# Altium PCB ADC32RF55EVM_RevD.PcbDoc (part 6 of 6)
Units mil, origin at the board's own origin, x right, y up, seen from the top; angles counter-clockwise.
Board outline 4190 x 2750 mil, 14 copper layers (Top Copper, Layer 2 (GND1), Layer 3 (PWR1), Layer 4 (GND2, Layer 5 (PWR2), Layer 6 (GND3), Layer 7 (SIG1), Layer 8 (GND4), Layer 9 (GND5), Layer 10 (SIG2), Layer 11 (GND6), Layer 12 (PWR3), Layer 13 (GND7), Bottom Copper), stack 58.6 mil thick; 427 components, 558 nets, 1902 pads, 1008 vias.
Unrouted connection lines stored in the file: 51.
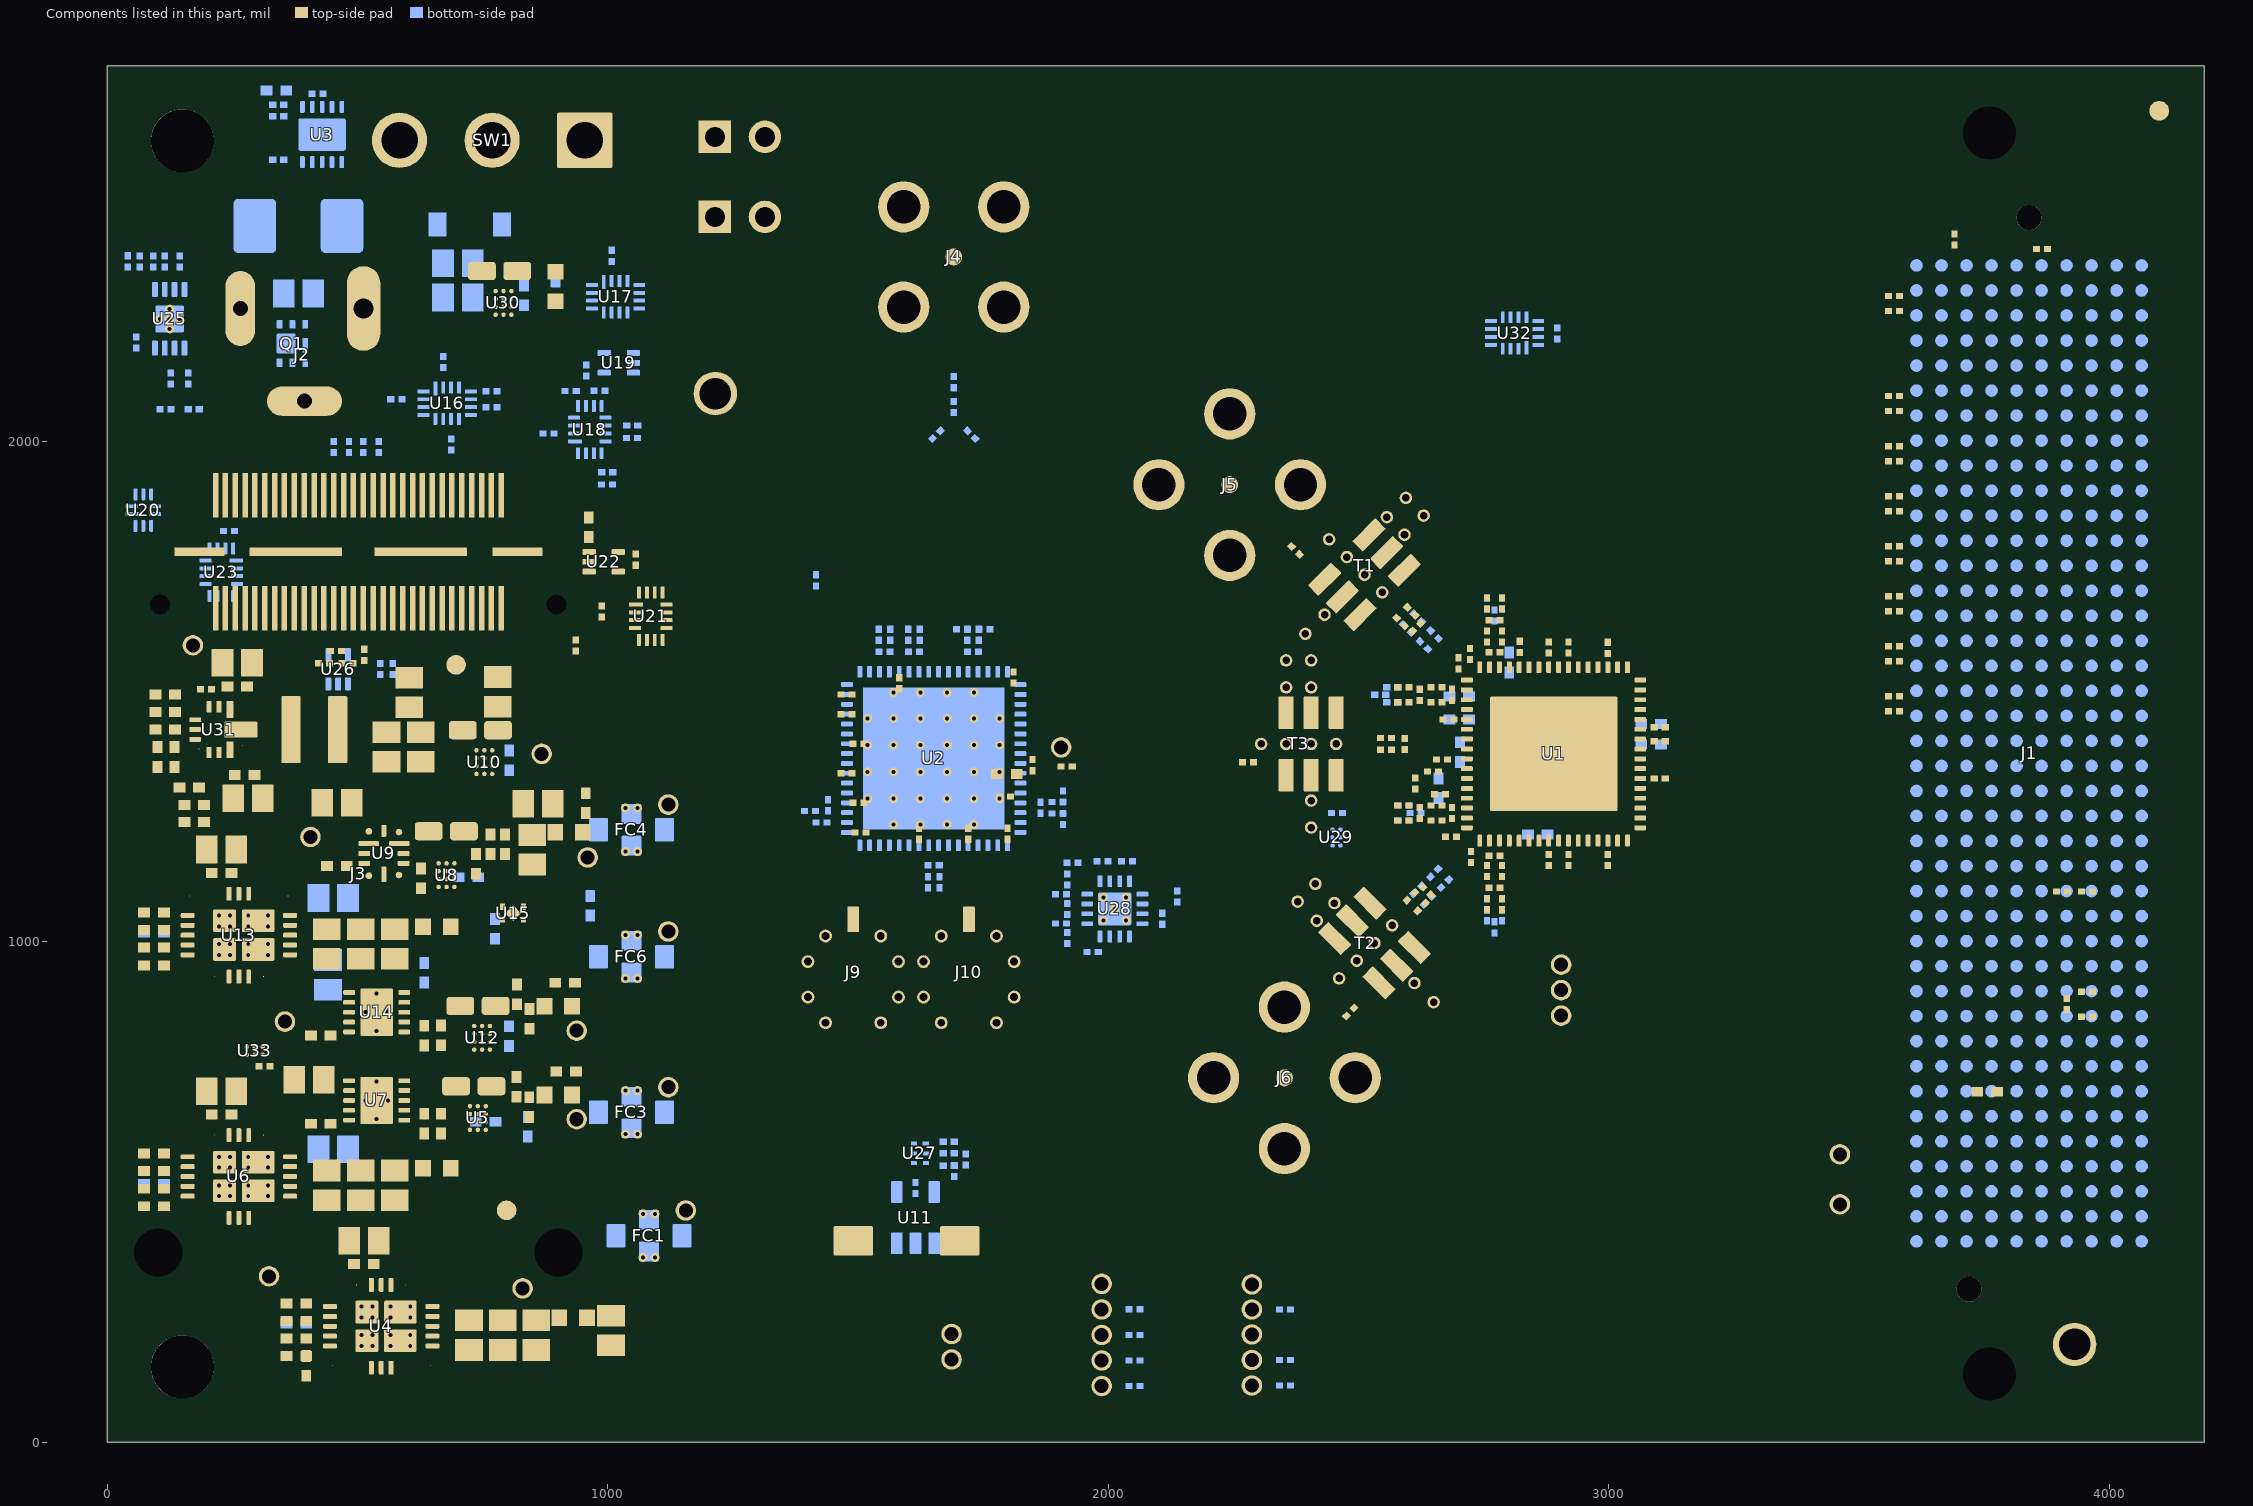
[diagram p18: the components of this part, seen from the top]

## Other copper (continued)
Layer 7 (SIG1):
  pour cut-out: 1303.31,625.21 ccw(c1303.31,631.94) 1310.04,631.94 1310.04,650.47 1310.04,698.71 ccw(c1303.31,698.71) 1303.31,705.45 1213.31,705.45 ccw(c1213.31,698.71) 1206.57,698.71 1206.57,631.94 ccw(c1213.31,631.94) 1213.31,625.21 1241.4,625.21
  pour cut-out: 3729.06,2099.94 ccw(c3745.06,2099.94) 3745.06,2083.94 ccw(c3745.06,2099.94) 3761.06,2099.94 ccw(c3745.06,2099.94) 3745.06,2115.94 ccw(c3745.06,2099.94)
  pour cut-out: 3729.06,2099.94 ccw(c3745.06,2099.94) 3745.06,2083.94 ccw(c3745.06,2099.94) 3761.06,2099.94 ccw(c3745.06,2099.94) 3745.06,2115.94 ccw(c3745.06,2099.94)
  pour cut-out: 3929.06,2099.94 ccw(c3945.06,2099.94) 3945.06,2083.94 ccw(c3945.06,2099.94) 3961.06,2099.94 ccw(c3945.06,2099.94) 3945.06,2115.94 ccw(c3945.06,2099.94)
  pour cut-out: 3929.06,2049.94 ccw(c3945.06,2049.94) 3945.06,2033.94 ccw(c3945.06,2049.94) 3961.06,2049.94 ccw(c3945.06,2049.94) 3945.06,2065.94 ccw(c3945.06,2049.94)
  pour cut-out: 3979.06,1399.94 ccw(c3995.06,1399.94) 3995.06,1383.94 ccw(c3995.06,1399.94) 4011.06,1399.94 ccw(c3995.06,1399.94) 3995.06,1415.94 ccw(c3995.06,1399.94)
  pour cut-out: 3979.06,1349.94 ccw(c3995.06,1349.94) 3995.06,1333.94 ccw(c3995.06,1349.94) 4011.06,1349.94 ccw(c3995.06,1349.94) 3995.06,1365.94 ccw(c3995.06,1349.94)
  pour cut-out: 3729.06,1899.94 ccw(c3745.06,1899.94) 3745.06,1883.94 ccw(c3745.06,1899.94) 3761.06,1899.94 ccw(c3745.06,1899.94) 3745.06,1915.94 ccw(c3745.06,1899.94)
  pour cut-out: 3729.06,1949.94 ccw(c3745.06,1949.94) 3745.06,1933.94 ccw(c3745.06,1949.94) 3761.06,1949.94 ccw(c3745.06,1949.94) 3745.06,1965.94 ccw(c3745.06,1949.94)
  pour cut-out: 3729.06,1949.94 ccw(c3745.06,1949.94) 3745.06,1933.94 ccw(c3745.06,1949.94) 3761.06,1949.94 ccw(c3745.06,1949.94) 3745.06,1965.94 ccw(c3745.06,1949.94)
  pour cut-out: 3729.06,1899.94 ccw(c3745.06,1899.94) 3745.06,1883.94 ccw(c3745.06,1899.94) 3761.06,1899.94 ccw(c3745.06,1899.94) 3745.06,1915.94 ccw(c3745.06,1899.94)
  pour cut-out: 3879.06,2199.94 ccw(c3895.06,2199.94) 3895.06,2183.94 ccw(c3895.06,2199.94) 3911.06,2199.94 ccw(c3895.06,2199.94) 3895.06,2215.94 ccw(c3895.06,2199.94)
  pour cut-out: 3879.06,2199.94 ccw(c3895.06,2199.94) 3895.06,2183.94 ccw(c3895.06,2199.94) 3911.06,2199.94 ccw(c3895.06,2199.94) 3895.06,2215.94 ccw(c3895.06,2199.94)
  pour cut-out: 3879.06,2149.94 ccw(c3895.06,2149.94) 3895.06,2133.94 ccw(c3895.06,2149.94) 3911.06,2149.94 ccw(c3895.06,2149.94) 3895.06,2165.94 ccw(c3895.06,2149.94)
  pour cut-out: 3879.06,2149.94 ccw(c3895.06,2149.94) 3895.06,2133.94 ccw(c3895.06,2149.94) 3911.06,2149.94 ccw(c3895.06,2149.94) 3895.06,2165.94 ccw(c3895.06,2149.94)
  pour cut-out: 3729.06,2049.94 ccw(c3745.06,2049.94) 3745.06,2033.94 ccw(c3745.06,2049.94) 3761.06,2049.94 ccw(c3745.06,2049.94) 3745.06,2065.94 ccw(c3745.06,2049.94)
  pour cut-out: 3729.06,2049.94 ccw(c3745.06,2049.94) 3745.06,2033.94 ccw(c3745.06,2049.94) 3761.06,2049.94 ccw(c3745.06,2049.94) 3745.06,2065.94 ccw(c3745.06,2049.94)
  pour cut-out: 4029.06,2299.94 ccw(c4045.06,2299.94) 4045.06,2283.94 ccw(c4045.06,2299.94) 4061.06,2299.94 ccw(c4045.06,2299.94) 4045.06,2315.94 ccw(c4045.06,2299.94)
  pour cut-out: 4029.06,2249.94 ccw(c4045.06,2249.94) 4045.06,2233.94 ccw(c4045.06,2249.94) 4061.06,2249.94 ccw(c4045.06,2249.94) 4045.06,2265.94 ccw(c4045.06,2249.94)
  pour cut-out: 4029.06,2099.94 ccw(c4045.06,2099.94) 4045.06,2083.94 ccw(c4045.06,2099.94) 4061.06,2099.94 ccw(c4045.06,2099.94) 4045.06,2115.94 ccw(c4045.06,2099.94)
  pour cut-out: 4029.06,2049.94 ccw(c4045.06,2049.94) 4045.06,2033.94 ccw(c4045.06,2049.94) 4061.06,2049.94 ccw(c4045.06,2049.94) 4045.06,2065.94 ccw(c4045.06,2049.94)
  pour cut-out: 4029.06,1899.94 ccw(c4045.06,1899.94) 4045.06,1883.94 ccw(c4045.06,1899.94) 4061.06,1899.94 ccw(c4045.06,1899.94) 4045.06,1915.94 ccw(c4045.06,1899.94)
  pour cut-out: 4029.06,1849.94 ccw(c4045.06,1849.94) 4045.06,1833.94 ccw(c4045.06,1849.94) 4061.06,1849.94 ccw(c4045.06,1849.94) 4045.06,1865.94 ccw(c4045.06,1849.94)
  pour cut-out: 4029.06,1699.94 ccw(c4045.06,1699.94) 4045.06,1683.94 ccw(c4045.06,1699.94) 4061.06,1699.94 ccw(c4045.06,1699.94) 4045.06,1715.94 ccw(c4045.06,1699.94)
  pour cut-out: 4029.06,1649.94 ccw(c4045.06,1649.94) 4045.06,1633.94 ccw(c4045.06,1649.94) 4061.06,1649.94 ccw(c4045.06,1649.94) 4045.06,1665.94 ccw(c4045.06,1649.94)
  pour cut-out: 4029.06,1499.94 ccw(c4045.06,1499.94) 4045.06,1483.94 ccw(c4045.06,1499.94) 4061.06,1499.94 ccw(c4045.06,1499.94) 4045.06,1515.94 ccw(c4045.06,1499.94)
  pour cut-out: 4029.06,1449.94 ccw(c4045.06,1449.94) 4045.06,1433.94 ccw(c4045.06,1449.94) 4061.06,1449.94 ccw(c4045.06,1449.94) 4045.06,1465.94 ccw(c4045.06,1449.94)
  pour cut-out: 3979.06,1799.94 ccw(c3995.06,1799.94) 3995.06,1783.94 ccw(c3995.06,1799.94) 4011.06,1799.94 ccw(c3995.06,1799.94) 3995.06,1815.94 ccw(c3995.06,1799.94)
  pour cut-out: 3979.06,1749.94 ccw(c3995.06,1749.94) 3995.06,1733.94 ccw(c3995.06,1749.94) 4011.06,1749.94 ccw(c3995.06,1749.94) 3995.06,1765.94 ccw(c3995.06,1749.94)
  pour cut-out: 3979.06,1599.94 ccw(c3995.06,1599.94) 3995.06,1583.94 ccw(c3995.06,1599.94) 4011.06,1599.94 ccw(c3995.06,1599.94) 3995.06,1615.94 ccw(c3995.06,1599.94)
  pour cut-out: 3979.06,1549.94 ccw(c3995.06,1549.94) 3995.06,1533.94 ccw(c3995.06,1549.94) 4011.06,1549.94 ccw(c3995.06,1549.94) 3995.06,1565.94 ccw(c3995.06,1549.94)
  pour cut-out: 291.53,2075.97 1062.72,2077.28 1175,1965 1175,1665 1358,1481.99 1358,785 1665.42,477.58 2351.57,477.58 2391.28,437.88 2391.28,221.18 1780.74,221.18 1697.28,137.72 1249.32,585.68 816.78,585.68 816.78,727.39 736.36,807.81 736.36,1065.15 765.49,1094.28 765.49,1179.04 746.36,1198.17 746.36,1430.3 698.54,1478.12 698.54,1562.02 539.01,1721.55 539.01,1828.49
  pour cut-out: 1348.62,2572.94 1348.62,2643 1278.84,2643 1278.84,2572.94
  pour cut-out: 819,2065 819,2127.01 788.97,2157.04 696.44,2157.04 640,2100.61 640,2065
  pour cut-out: 3052.35,1210.93 3052.35,1217 2868.15,1217 2868.15,1210.93
  pour cut-out: 1761.09,1630.25 1761.09,1635.77 1694.7,1635.77 1694.7,1630.25
  pour cut-out: 1023.91,2188.95 1047.49,2212.53 1000.97,2259.06 977.39,2235.48
  pour cut-out: 3573.07,2169.46 3573.07,1909.72 3580,1909.72 3580,2171
  text ".Layer_Name" at 576,-853 h60
Layer 13 (GND7):
  text ".Layer_Name" at 576,-854 h60
Bottom Copper:
  drawing of 71 lines, arcs and shapes, not listed
  text ".Layer_Name" at 573,-851 h60
Multi-Layer:
  pour cut-out: 2247.3,1358.28 ccw(c2235.65,1358.28) 2235.65,1369.93 ccw(c2235.65,1358.84) 2224.57,1358.84 2224.57,1358.35 ccw(c2235.97,1358.35) 2235.97,1346.95 ccw(c2235.97,1358.28)
  pour cut-out: 913,645 ccw(c938,645) 938,620 ccw(c938,645) 963,645 ccw(c938,645) 938,670 ccw(c938,645)
  pour cut-out: 935.01,1168.14 ccw(c960.01,1168.14) 960.01,1143.14 ccw(c960.01,1168.14) 985.01,1168.14 ccw(c960.01,1168.14) 960.01,1193.14 ccw(c960.01,1168.14)
  pour cut-out: 912.96,821.88 ccw(c937.96,821.88) 937.96,796.88 ccw(c937.96,821.88) 962.96,821.88 ccw(c937.96,821.88) 937.96,846.88 ccw(c937.96,821.88)
  pour cut-out: 1096,709 ccw(c1121,709) 1121,684 ccw(c1121,709) 1146,709 ccw(c1121,709) 1121,734 ccw(c1121,709)
  pour cut-out: 1096,1020.26 ccw(c1121,1020.26) 1121,995.26 ccw(c1121,1020.26) 1146,1020.26 ccw(c1121,1020.26) 1121,1045.26 ccw(c1121,1020.26)
  pour cut-out: 1096,1273.74 ccw(c1121,1273.74) 1121,1248.74 ccw(c1121,1273.74) 1146,1273.74 ccw(c1121,1273.74) 1121,1298.74 ccw(c1121,1273.74)
  pour cut-out: 1131,462.76 ccw(c1156,462.76) 1156,437.76 ccw(c1156,462.76) 1181,462.76 ccw(c1156,462.76) 1156,487.76 ccw(c1156,462.76)
  pour cut-out: 843,1375 ccw(c868,1375) 868,1350 ccw(c868,1375) 893,1375 ccw(c868,1375) 868,1400 ccw(c868,1375)
  pour cut-out: 3929.06,2099.94 ccw(c3945.06,2099.94) 3945.06,2083.94 ccw(c3945.06,2099.94) 3961.06,2099.94 ccw(c3945.06,2099.94) 3945.06,2115.94 ccw(c3945.06,2099.94)
  pour cut-out: 3929.06,2049.94 ccw(c3945.06,2049.94) 3945.06,2033.94 ccw(c3945.06,2049.94) 3961.06,2049.94 ccw(c3945.06,2049.94) 3945.06,2065.94 ccw(c3945.06,2049.94)
  pour cut-out: 3729.06,2099.94 ccw(c3745.06,2099.94) 3745.06,2083.94 ccw(c3745.06,2099.94) 3761.06,2099.94 ccw(c3745.06,2099.94) 3745.06,2115.94 ccw(c3745.06,2099.94)
  pour cut-out: 3729.06,2049.94 ccw(c3745.06,2049.94) 3745.06,2033.94 ccw(c3745.06,2049.94) 3761.06,2049.94 ccw(c3745.06,2049.94) 3745.06,2065.94 ccw(c3745.06,2049.94)
  pour cut-out: 3729.06,1899.94 ccw(c3745.06,1899.94) 3745.06,1883.94 ccw(c3745.06,1899.94) 3761.06,1899.94 ccw(c3745.06,1899.94) 3745.06,1915.94 ccw(c3745.06,1899.94)
  pour cut-out: 3729.06,1949.94 ccw(c3745.06,1949.94) 3745.06,1933.94 ccw(c3745.06,1949.94) 3761.06,1949.94 ccw(c3745.06,1949.94) 3745.06,1965.94 ccw(c3745.06,1949.94)
  pour cut-out: 3979.06,1399.94 ccw(c3995.06,1399.94) 3995.06,1383.94 ccw(c3995.06,1399.94) 4011.06,1399.94 ccw(c3995.06,1399.94) 3995.06,1415.94 ccw(c3995.06,1399.94)
  pour cut-out: 3979.06,1349.94 ccw(c3995.06,1349.94) 3995.06,1333.94 ccw(c3995.06,1349.94) 4011.06,1349.94 ccw(c3995.06,1349.94) 3995.06,1365.94 ccw(c3995.06,1349.94)
  pour cut-out: 3879.06,2199.94 ccw(c3895.06,2199.94) 3895.06,2183.94 ccw(c3895.06,2199.94) 3911.06,2199.94 ccw(c3895.06,2199.94) 3895.06,2215.94 ccw(c3895.06,2199.94)
  pour cut-out: 3879.06,2149.94 ccw(c3895.06,2149.94) 3895.06,2133.94 ccw(c3895.06,2149.94) 3911.06,2149.94 ccw(c3895.06,2149.94) 3895.06,2165.94 ccw(c3895.06,2149.94)
  pour cut-out: 3807,2445.49 ccw(c3840,2445.49) 3840,2412.49 ccw(c3840,2445.49) 3873,2445.49 ccw(c3840,2445.49) 3840,2478.49 ccw(c3840,2445.49)
  pour cut-out: 3687,304.49 ccw(c3720,304.49) 3720,271.49 ccw(c3720,304.49) 3753,304.49 ccw(c3720,304.49) 3720,337.49 ccw(c3720,304.49)
  pour cut-out: 4029.06,2099.94 ccw(c4045.06,2099.94) 4045.06,2083.94 ccw(c4045.06,2099.94) 4061.06,2099.94 ccw(c4045.06,2099.94) 4045.06,2115.94 ccw(c4045.06,2099.94)
  pour cut-out: 4029.06,2299.94 ccw(c4045.06,2299.94) 4045.06,2283.94 ccw(c4045.06,2299.94) 4061.06,2299.94 ccw(c4045.06,2299.94) 4045.06,2315.94 ccw(c4045.06,2299.94)
  pour cut-out: 4029.06,2049.94 ccw(c4045.06,2049.94) 4045.06,2033.94 ccw(c4045.06,2049.94) 4061.06,2049.94 ccw(c4045.06,2049.94) 4045.06,2065.94 ccw(c4045.06,2049.94)
  pour cut-out: 3979.06,1799.94 ccw(c3995.06,1799.94) 3995.06,1783.94 ccw(c3995.06,1799.94) 4011.06,1799.94 ccw(c3995.06,1799.94) 3995.06,1815.94 ccw(c3995.06,1799.94)
  pour cut-out: 3979.06,1749.94 ccw(c3995.06,1749.94) 3995.06,1733.94 ccw(c3995.06,1749.94) 4011.06,1749.94 ccw(c3995.06,1749.94) 3995.06,1765.94 ccw(c3995.06,1749.94)
  pour cut-out: 3979.06,1599.94 ccw(c3995.06,1599.94) 3995.06,1583.94 ccw(c3995.06,1599.94) 4011.06,1599.94 ccw(c3995.06,1599.94) 3995.06,1615.94 ccw(c3995.06,1599.94)
  pour cut-out: 3979.06,1549.94 ccw(c3995.06,1549.94) 3995.06,1533.94 ccw(c3995.06,1549.94) 4011.06,1549.94 ccw(c3995.06,1549.94) 3995.06,1565.94 ccw(c3995.06,1549.94)
  pour cut-out: 4029.06,2249.94 ccw(c4045.06,2249.94) 4045.06,2233.94 ccw(c4045.06,2249.94) 4061.06,2249.94 ccw(c4045.06,2249.94) 4045.06,2265.94 ccw(c4045.06,2249.94)
  pour cut-out: 4029.06,1899.94 ccw(c4045.06,1899.94) 4045.06,1883.94 ccw(c4045.06,1899.94) 4061.06,1899.94 ccw(c4045.06,1899.94) 4045.06,1915.94 ccw(c4045.06,1899.94)
  pour cut-out: 4029.06,1849.94 ccw(c4045.06,1849.94) 4045.06,1833.94 ccw(c4045.06,1849.94) 4061.06,1849.94 ccw(c4045.06,1849.94) 4045.06,1865.94 ccw(c4045.06,1849.94)
  pour cut-out: 4029.06,1699.94 ccw(c4045.06,1699.94) 4045.06,1683.94 ccw(c4045.06,1699.94) 4061.06,1699.94 ccw(c4045.06,1699.94) 4045.06,1715.94 ccw(c4045.06,1699.94)
  pour cut-out: 4029.06,1649.94 ccw(c4045.06,1649.94) 4045.06,1633.94 ccw(c4045.06,1649.94) 4061.06,1649.94 ccw(c4045.06,1649.94) 4045.06,1665.94 ccw(c4045.06,1649.94)
  pour cut-out: 4029.06,1499.94 ccw(c4045.06,1499.94) 4045.06,1483.94 ccw(c4045.06,1499.94) 4061.06,1499.94 ccw(c4045.06,1499.94) 4045.06,1515.94 ccw(c4045.06,1499.94)
  pour cut-out: 4029.06,1449.94 ccw(c4045.06,1449.94) 4045.06,1433.94 ccw(c4045.06,1449.94) 4061.06,1449.94 ccw(c4045.06,1449.94) 4045.06,1465.94 ccw(c4045.06,1449.94)

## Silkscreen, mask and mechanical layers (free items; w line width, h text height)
Top SilkScreen:
  circle w1: c901.75,378.79 r72
  circle w1: c101.75,378.8 r72
  lines w4: 2464.05,1194.22 2581.47,1196.14 ; 2464.05,1555.78 2581.47,1553.86 ; 2536.18,1433.05 2549.82,1418.95 ; 2544.08,1419.05 2549.82,1418.95 ; 2549.91,1424.7 2549.82,1418.95 ; 2581.47,1196.55 2609,1225 ; 2581.47,1553.45 2609,1525 ; 2599.68,1224.85 2609,1225 ; 2599.68,1525.15 2609,1525 ; 2609.15,1215.68 2609,1225 ; 2609.15,1534.32 2609,1525
  lines w5: 1653.38,130 1828,130 1828,253.62 1653.38,253.62 1653.38,130 ; 1953.38,78.26 2150.75,78.26 2150.75,352 1953.38,352 1953.38,78.26 ; 2253.38,78.26 2450.75,78.26 2450.75,352 2253.38,352 2253.38,78.26 ; 2871.38,817.26 3123,817.26 3123,996 2871.38,996 2871.38,817.26
  text "SPI" at 1161.51,2673.01 h40
  text "INSTALL=USB" at 1421,2664 h35
  text "ADC32RF55" at 2149,2606 h80
  text "EVM" at 2912.24,2605.82 h80
  text "UNINSTALL=FMC" at 1421,2601 h35
  text "PLUG" at 531,2509 h40 r90
  text "REV D" at 2136,2504 h60
  text "FMC" at 1124,2503 h40 r90
  text "+12V" at 222.84,2472.99 h40
  text "DC142D" at 2136,2424 h60
  text "+12V Select" at 575.32,2412.43 h40
  text "GPIO" at 1163.21,2335.01 h40
  text "+12V" at 836.12,2192.22 h30
  text "EXTCLK" at 1540,2119 h50
  text "GND" at 1163.44,1970.14 h40
  text "LMK" at 1940.51,1412.13 h30
  text "DVDD" at 860.43,1407.98 h40
  text "SYNC" at 1940,1370 h30
  text "+1.2V" at 906.85,1356.96 h30
  text "AVDD12" at 1103.89,1308.37 h40
  text "+1.2V" at 1152.89,1264.37 h30
  text "+2.1V" at 295,1230 h20
  text "+1.2V" at 995,1160 h20
  text "AVDD18" at 1106.01,1053.82 h40
  text "+1.8V" at 1151.72,1010.8 h30
  text "+2.7V" at 240,840 h20
  text "+1.8V" at 965,815 h20
  text "ADC" at 2954.35,763.51 h35
  text "SYSREF_P" at 1388.09,762 h25
  text "SYSREF_N" at 1619.19,762 h25
  text "CLKVDD" at 1095.89,743.37 h40
  text "+1.2V" at 1151.85,701.96 h30
  text "+1.2V" at 895,590 h20
  text "3p3V_Util" at 1069.41,507.63 h40
  text "+3.3V" at 1191.22,450.67 h30
  text "LMK" at 2008.35,369.51 h35
  text "ADC" at 2308.35,369.51 h35
  text "+3.3V" at 725,355 h20
  text "+12V" at 219.81,313.08 h20
  text "I2C" at 1697.26,271.51 h35
  text "GND" at 3877.68,70.01 h40
  text ".Layer_Name" at 575,-856 h60
Bottom Silk:
  circle w10: c1692,397 r1
  circle w10: c385,2690 r4.24
  lines w4: 1582.94,557.94 1607.57,533.3 ; 1598,533.22 1607.57,533.3 ; 1607.49,542.87 1607.57,533.3
  lines w5: 1544,128 1723.62,128 1723.62,252.62 1544,252.62 1544,128 ; 1826.25,77.26 2023.62,77.26 2023.62,352 1826.25,352 1826.25,77.26 ; 2123.25,78.26 2320.62,78.26 2320.62,352 2123.25,352 2123.25,78.26 ; 2686.62,818.02 2938.25,818.02 2938.25,996.77 2686.62,996.77 2686.62,818.02
  text "CW" at 3806.42,2578.78 h40 r180
  text "K1" at 3620,2493 h25
  text "A1" at 4077.3,2491.1 h25
  text "LMK" at 2028.49,1475.13 h30
  text "SYNC" at 2029,1433 h30
  text "ADC" at 2852.65,767.51 h35
  text "ADC" at 2271.65,367.51 h35
  text "LMK" at 1974.65,366.51 h35
  text "I2C" at 1677.74,267.51 h35
  text "A40" at 4099.61,237.08 h25
  text "K40" at 3647.61,236.16 h25
  text ".Layer_Name" at 576,-854 h60
Top Paste:
  region: 3247.96,1270.31 ccw(c3257.96,1270.31) 3257.96,1260.31 3317.54,1260.31 3317.99,1260.34 ccw(c3317.99,1270.31) 3327.96,1270.31 3327.96,1320.38 ccw(c3317.03,1320.38) 3317.03,1331.31 3257.96,1331.31 ccw(c3257.96,1321.31) 3247.96,1321.31 3247.96,1270.31 cw(c3247.96,1270.31)
  region: 3247.96,1349.15 ccw(c3257.96,1349.15) 3257.96,1339.16 3317.54,1339.16 3317.99,1339.18 ccw(c3317.99,1349.16) 3327.96,1349.16 3327.96,1399.22 ccw(c3317.03,1399.22) 3317.03,1410.16 3257.96,1410.16 ccw(c3257.96,1400.16) 3247.96,1400.16 3247.96,1349.16 cw(c3247.96,1349.16)
  region: 3247.96,1428 ccw(c3257.96,1428) 3257.96,1418 3317.54,1418 3317.99,1418.03 ccw(c3317.99,1428) 3327.96,1428 3327.96,1478.07 ccw(c3317.03,1478.07) 3317.03,1489 3257.96,1489 ccw(c3257.96,1479) 3247.96,1479 3247.96,1428 cw(c3247.96,1428)
  region: 3160.48,1428 ccw(c3170.48,1428) 3170.48,1418 3230.06,1418 3230.51,1418.03 ccw(c3230.51,1428) 3240.48,1428 3240.48,1478.07 ccw(c3229.55,1478.07) 3229.55,1489 3170.48,1489 ccw(c3170.48,1479) 3160.48,1479 3160.48,1428 cw(c3160.48,1428)
  region: 3073,1349.15 ccw(c3083,1349.15) 3083,1339.16 3142.58,1339.16 3143.03,1339.18 ccw(c3143.03,1349.16) 3153,1349.16 3153,1399.22 ccw(c3142.07,1399.22) 3142.07,1410.16 3083,1410.16 ccw(c3083,1400.16) 3073,1400.16 3073,1349.16 cw(c3073,1349.16)
  region: 3073,1428 ccw(c3083,1428) 3083,1418 3142.58,1418 3143.03,1418.03 ccw(c3143.03,1428) 3153,1428 3153,1478.07 ccw(c3142.07,1478.07) 3142.07,1489 3083,1489 ccw(c3083,1479) 3073,1479 3073,1428 cw(c3073,1428)
  region: 3073,1270.31 ccw(c3083,1270.31) 3083,1260.31 3142.58,1260.31 3143.03,1260.34 ccw(c3143.03,1270.31) 3153,1270.31 3153,1320.38 ccw(c3142.07,1320.38) 3142.07,1331.31 3083,1331.31 ccw(c3083,1321.31) 3073,1321.31 3073,1270.31 cw(c3073,1270.31)
  region: 3160.48,1349.15 ccw(c3170.48,1349.15) 3170.48,1339.16 3230.06,1339.16 3230.51,1339.18 ccw(c3230.51,1349.16) 3240.48,1349.16 3240.48,1399.22 ccw(c3229.55,1399.22) 3229.55,1410.16 3170.48,1410.16 ccw(c3170.48,1400.16) 3160.48,1400.16 3160.48,1349.16 cw(c3160.48,1349.16)
  region: 3160.48,1270.31 ccw(c3170.48,1270.31) 3170.48,1260.31 3230.06,1260.31 3230.51,1260.34 ccw(c3230.51,1270.31) 3240.48,1270.31 3240.48,1320.38 ccw(c3229.55,1320.38) 3229.55,1331.31 3170.48,1331.31 ccw(c3170.48,1321.31) 3160.48,1321.31 3160.48,1270.31 cw(c3160.48,1270.31)
  text ".Layer_Name" at 581,-857 h60
Bottom Paste:
  text ".Layer_Name" at 573,-854 h60
Top Solder Mask:
  rectangle: 2758,1255 3023,1494
  text ".Layer_Name" at 581,-858 h60
Bottom Solder Mask:
  text ".Layer_Name" at 576,-854 h60
Drill Guide:
  pour cut-out: 1436.98,2550 ccw(c1462.98,2550) 1462.98,2524 ccw(c1462.98,2550) 1488.98,2550 ccw(c1462.98,2550) 1462.98,2576 ccw(c1462.98,2550)
M1 Board Outline:
  the board outline again, w5
M2 Board Dimensions:
  text ".Layer_Name" at 3907.48,-846.46 h60
M3 3D STEP Top:
  text ".Layer_Name" at 577,-858.49 h60
M4 3D STEP Bottom:
  text ".Layer_Name" at 577,-858.49 h60
M5 Assembly Top:
  lines w10: -292,-930.17 6308,-930.17 ; -292,-726.83 6310,-726.83 ; -292,-523.5 -292,-1133.5 3713,-1133.5 6310,-1133.5 6310,-523.5 -291.5,-523.5 -291.5,-1133.5 1284,-1133.5 ; 2173,-1133.5 2173,-523.5 ; 3440,-726.83 3440,-523.5 ; 4280,-726.83 4280,-523.5 ; 4902,-1140 4902,-937.17
  text "COMPONENTS MARKED 'DNP' SHOULD NOT BE POPULATED." at 1153.5,-318.5 h60
  text "ASSEMBLY VARIANT:" at 1153,-434 h60
  text ".VariantName" at 2189,-434 h60
  text "PCB VIEWED FROM TOP SIDE" at -228.5,-655.67 h60
  text "BOARD #:" at 2248,-655.67 h60
  text ".PRJ_Number" at 2793.5,-655.67 h60
  text "REV:" at 3638,-655.67 h60
  text ".PCB_Rev" at 3929.5,-655.67 h60
  text "SVN REV:" at 4476,-655.67 h60
  text ".VersionControl_RevNumber" at 4982,-655.67 h60
  text "PLOT NAME =" at -228.5,-1064.34 h60
  text "N/A" at 577,-1064.34 h60
  text "TEXAS INSTRUMENTS" at 5113,-1064.34 h60
  text "GENERATED    :" at 2250.58,-1072.83 h60
  text ".Print_Date" at 3120.08,-1072.83 h60
  text ".Print_Time" at 3849.08,-1072.83 h60
M6 Assembly Bottom:
  lines w10: -292.5,-727.33 6309.5,-727.33 ; -290.5,-930.67 6309.5,-930.67 ; 1115.5,-1140.5 1115.5,-937.67 ; 1737.5,-727.33 1737.5,-524 ; 2577.5,-727.33 2577.5,-524 ; 3844.5,-1134 3844.5,-524 ; 4733.5,-1134 6309,-1134 6309,-524 -292.5,-524 -292.5,-1134 2304.5,-1134 6309.5,-1134 6309.5,-524
  text "COMPONENTS MARKED 'DNP' SHOULD NOT BE POPULATED." at 6102,-318 h60
  text ".VariantName" at 5058,-434 h60
  text "ASSEMBLY VARIANT:" at 6097,-434 h60
  text ".VersionControl_RevNumber" at 1180,-650 h60
  text "SVN REV:" at 1541.5,-656.17 h60
  text ".PCB_Rev" at 2088,-656.17 h60
  text "REV:" at 2379.5,-656.17 h60
  text ".PRJ_Number" at 3224,-656.17 h60
  text "BOARD #:" at 3769.5,-656.17 h60
  text "PCB VIEWED FROM BOTTOM SIDE" at 6246,-656.17 h60
  text "TEXAS INSTRUMENTS" at 904.5,-1064.84 h60
  text ".Print_Time" at 2169,-1064.84 h60
  text ".Print_Date" at 2898,-1064.84 h60
  text "GENERATED    :" at 3767.5,-1064.84 h60
  text "N/A" at 5440.5,-1064.84 h60
  text "PLOT NAME =" at 6246,-1064.84 h60
M9 Title Sheet:
  drawing of 57 lines, arcs and shapes, not listed
  text "1" at 739.84,8036.5 h70
  text "2" at 3235.5,8036.5 h70
  text "3" at 5724.84,8036.5 h70
  text "4" at 8231.51,8036.5 h70
  text "5" at 10730.5,8036.5 h70
  text "6" at 13235.5,8036.5 h70
  text "A" at -416.5,6893.5 h70
  text "B" at -416.5,4513.5 h70
  text "B" at 14383.5,4513.5 h70
  text "C" at -416.5,2138.5 h70
  text "C" at 14383.5,2138.5 h70
  text "PROJECT TITLE:" at 11343.5,277.5 h45
  text ".PRJ_Title" at 11393.5,144.17 h70
  text "DESIGNED FOR:" at 11343.5,-23.5 h45
  text "TI" at 11393.5,-163.5 h70
  text "D" at 14383.5,-231.5 h70
  text "FILE NAME:" at 11343.5,-323.5 h45
  text ".PRJ_Title" at 11393.5,-443.5 h70
  text "Texas Instruments (TI) and/or its licensors do not warrant the accuracy or completeness of this specification" at 6374,-605.34 h45
  text "ENGINEER:" at 11343.5,-613.5 h45
  text "LAYOUT BY:" at 12848.5,-613.5 h45
  text "or any information contained therein. TI and/or its licensors do not warrant that this design will meet" at 6329.01,-718 h45
  text ".PRJ_Engineer" at 11393.5,-768.49 h70
  text ".PCB_Layout" at 12899,-768.49 h70
  text "the specifications, will be suitable for your application or fit for any particular purpose, or will operate in" at 6329.01,-830.67 h45
  text "ALTIUM DESIGNER VERSION:" at 12848.5,-923.5 h45
  text "an implementation. TI and/or its licensors do not warrant that the design is production worthy. You should" at 6329.01,-943.33 h45
  text "completely validate and test your design implementation to confirm the system functionality for your application." at 6374,-1056 h45
  text "print_Scale: 1:1" at 11393.5,-1056.83 h70
  text ".Application_BuildNumber" at 12899,-1056.83 h70
  text "1" at 739.84,-1263.5 h70
  text "2" at 3235.5,-1263.5 h70
  text "3" at 5724.84,-1263.5 h70
  text "4" at 8231.51,-1263.5 h70
  text "5" at 10730.5,-1263.5 h70
  text "6" at 13235.5,-1263.5 h70
M10 Fab Notes:
  drawing of 221 lines, arcs and shapes, not listed
  text "DESIGN INFORMATION" at 12392.02,7934.98 h60
  text "MIN. TRACK WIDTH:" at 11747.46,7802.85 h60
  text "MIL" at 12998.46,7802.85 h60
  text "3.7" at 12790,7795 h60
  text "MIN. CLEARANCE:" at 11747.46,7678.73 h60
  text "MIL" at 12998.46,7678.73 h60
  text "5" at 12843.92,7677.09 h60
  text "MIN. VIA PAD SIZE:" at 11747.46,7554.6 h60
  text "16" at 12813.71,7554.6 h60
  text "MIL" at 12998.46,7554.6 h60
  text "0.05mm (2MIL)" at 12442.46,7424.7 h60
  text "MINIMUM ANNULAR RING" at 11418.23,7416.48 h60
  text "EXTERNAL" at 13150.46,7416.48 h60
  text "PER" at 11618.23,7306.35 h60
  text "IPC-D-275 CLASS 2 LEVEL C" at 11838.23,7306.35 h60
  text "MIL, HOLES" at 13326.46,7205.87 h60
  text "+/-" at 12934,7197.29 h60
  text "+/-" at 13788,7197.29 h60
  text "REGISTRATION TOLERANCES:" at 11418.23,7196.22 h60
  text "METAL" at 12618,7196.22 h60
  text "5" at 13194.2,7196.22 h60
  text "3" at 14027.2,7196.22 h60
  text "MIL" at 14143.46,7196.22 h60
  text "HOLE SIZE TOLERANCE (UNLESS OTHERWISE SPECIFIED):" at 11418.23,7097.91 h60
  text "+/-" at 13788,7095.03 h60
  text "3" at 14027.2,7093.97 h60
  text "MIL" at 14143.46,7093.97 h60
  text "MATERIAL:" at 11343.46,6956.32 h60
  text "ISOLA FR4-370HR" at 12329.9,6827.8 h60
  text "FR-408" at 11764.46,6814.15 h60
  text "Isola I-Speed" at 12329.9,6630.95 h60
  text "Meg4" at 11764.46,6618.44 h60
  text "Isola MT-40" at 12329.9,6434.1 h60
  text "Nelco MW-1000" at 13314.15,6434.1 h60
  text "Meg6" at 11764.46,6421.59 h60
  text "Meg4 & Isola FR4-370HR" at 12134.36,6233.49 h60
  text "X" at 11625,6229 h60
  text "OTHER" at 11804.46,6224.74 h60
  text "62 MIL (1.6mm) +/-10%" at 12084.56,6081.71 h60
  text "X" at 11964.46,6079.26 h60
  text "THICKNESS:" at 11418.23,6073.49 h60
  text "OTHER" at 13369.46,6073.49 h60
  text "TOLERANCE:" at 11418.23,5935.17 h60
  text "X" at 12266.46,5935.17 h60
  text "ANSI IPC-6012 TYPE 3 CLASS 2" at 12444.48,5935.17 h60
  text "OTHER +/-" at 12444.46,5790.99 h60
  text "BOW & TWIST:" at 11418.23,5645.8 h60
  text "X" at 12266.46,5645.8 h60
  text "ANSI IPC-6012 TYPE 3 CLASS 2" at 12444.48,5645.8 h60
  text "OTHER +/-" at 12444.46,5499.1 h60
  text "DRILLING:" at 11343.46,5368.48 h60
  text "NC_DRILL FILES" at 13104.46,5263.29 h60
  text "REFERENCE:" at 11418.23,5259.36 h60
  text "X" at 12075.46,5259.26 h60
  text "AS SHOWN" at 12253.46,5259.36 h60
  text "X" at 12976.46,5259.36 h60
  text "OTHER" at 13402.46,5117.1 h60
  text "PTH COPPER THICKNESS:" at 11417.91,5113.57 h60
  text "X" at 12557.14,5113.57 h60
  text "20-30 um" at 12685.14,5113.57 h60
  text "BOARD FINISH:" at 11343.46,4965.98 h60
  text "SILKSCREEN:" at 11498.68,4855.85 h60
  text "X" at 12456.46,4855.85 h60
  text "TOP" at 12573.46,4855.85 h60
  text "X" at 12966.46,4855.85 h60
  text "BOTTOM" at 13084.46,4855.85 h60
  text "X" at 12461,4703 h60
  text "SILKSCREEN COLOR:" at 11498.68,4700.66 h60
  text "WHITE" at 12573.46,4700.66 h60
  text "OTHER" at 13084.46,4700.66 h60
  text "X" at 13175,4565 h60
  text "GREEN" at 12704.46,4557.21 h60
  text "OTHER" at 13322.46,4557.21 h60
  text "RED" at 13752.46,4552.21 h60
  text "SOLDER RESIST COLOR:" at 11498.68,4550.35 h60
  text "X" at 12586.46,4402.96 h60
  text "MATTE" at 12704.46,4402.96 h60
  text "SEMI-GLOSS" at 13322,4402.32 h60
  text "IMMERSION GOLD (ENIG)" at 12404.46,4230.19 h60
  text "ENEPIG" at 13742,4222.97 h60
  text "SURFACE FINISH:" at 11343.46,4221.97 h60
  text "X" at 12226.46,4221.97 h60
  text "IMM. TIN/SILVER OR EQUIV" at 11673,4084.65 h60
  text "HARD GOLD (30u)" at 13104.46,4080.72 h60
  text "OTHER" at 11698,3883.87 h60
  text "ARRAY/PANEL:" at 11343.46,3728.49 h60
  text "CUT AND TRIM PER M1 BOARD OUTLINE" at 12404.46,3720.27 h60
  text "N.C. ROUTE" at 12404.46,3584.3 h60
  text "X" at 13092.46,3584.3 h60
  text "V. SCORE" at 13270.46,3584.3 h60
  text "CERTIFICATION:" at 11343.46,3455.17 h60
  text "MATERIALS AND WORKMANSHIP FOR ALL PCBS" at 12068.46,3455.17 h60
  text "TO MEET OR EXCEED THE REQUIREMENTS OF:" at 12068.46,3361.11 h60
  text "X" at 11705.97,3232.48 h60
  text "ANSI IPC-A-600F CLASS ->" at 11833.96,3232.48 h60
  text "X" at 13481.97,3232.48 h60
  text "2" at 13591.96,3232.48 h60
  text "1" at 13276.96,3230.98 h60
  text "3" at 13945.96,3230.98 h60
  text "X" at 12517.97,3084.8 h60
  text "RoHS" at 12645.96,3084.8 h60
  text "OTHER" at 13290.36,3084.8 h60
  text "PER ORDER" at 13687.42,3084.8 h60
  text "ALL BOARDS MUST MEET OR EXCEED UL94-V0 REQUIREMENTS." at 11371,2930.97 h60
  text "PCB MUST BEAR THE UL94V-0 UL REGISTERED MATERIAL ID NUMBER" at 11371,2814.91 h60
  text "ADDITIONAL REQUIREMENTS:" at 11343.46,2645.48 h60
  text "MICROSECTION:" at 11418.23,2538.36 h60
  text "YES" at 12323.96,2538.36 h60
  text "REQUIRED" at 13185.46,2394.02 h60
  text "BARE BOARD ELEC. TEST:" at 11418.23,2391.17 h60
  text "NONE" at 12723.96,2391.17 h60
  text "X" at 13067.46,2391.17 h60
  text "PER ORDER" at 13777.46,2391.17 h60
  text "X" at 11459.08,2200.71 h60
  text "16 MIL & SMALLER VIAS REQUIRE NON-CONDUCTIVE FILL AND PLANARIZE" at 11570.3,2110.16 h59
  text "X" at 11459.08,1995.71 h60
  text "OUTER LAYER TRACKS 10 MIL WIDE REQUIRE 50 OHM SINGLE-ENDED IMPEDANCE" at 11573.25,1899.53 h60
  text "X" at 11459.08,1795.71 h60
  text "OUTER LAYER TRACKS 7 MIL WIDE WITH 5 MIL AIRGAP REQUIRE 100 OHM DIFFERENTIAL IMPEDANCE" at 11573.25,1694.8 h60
  text "INNER LAYER 03 & 12 TRACKS 4 MIL WIDE REQUIRE 50 OHM SINGLE-ENDED IMPEDANCE" at 11573.25,1490.08 h60
  text "X" at 11459.08,1385.71 h60
  text "INNER LAYER 07 TRACKS 4 MIL WIDE WITH  6 MIL AIRGAP REQUIRE 100 OHM DIFFERENTIAL IMPEDANCE" at 11567.35,1296.18 h60
  text "NO VENDOR LOGO OR NAME ON THE BOARD" at 11567.35,1157.15 h60
M11 Gerber Information:
  lines w10: -292,-930.17 6308,-930.17 ; -292,-726.83 6310,-726.83 ; -292,-523.5 -292,-1133.5 3713,-1133.5 6310,-1133.5 6310,-523.5 -291.5,-523.5 -291.5,-1133.5 1284,-1133.5 ; 2173,-1133.5 2173,-523.5 ; 3440,-726.83 3440,-523.5 ; 4280,-726.83 4280,-523.5 ; 4902,-1140 4902,-937.17
  text "BOARD #:" at 2248,-655.67 h60
  text ".PRJ_Number" at 2793.5,-655.67 h60
  text "REV:" at 3638,-655.67 h60
  text ".PCB_Rev" at 3929.5,-655.67 h60
  text "SVN REV:" at 4476,-655.67 h60
  text ".VersionControl_RevNumber" at 4982,-655.67 h60
  text "ALL ARTWORK VIEWED FROM TOP SIDE" at -224,-668 h60
  text "LAYER NAME =" at -228.5,-858.49 h60
  text "PLOT NAME =" at -228.5,-1064.34 h60
  text ".plot_File_Name" at 577,-1064.34 h40
  text "GENERATED    :" at 2250,-1064.34 h60
  text ".Print_Date" at 3119.5,-1064.34 h60
  text ".Print_Time" at 3848.5,-1064.34 h60
  text "TEXAS INSTRUMENTS" at 5113,-1064.34 h60
M12 Stackup:
  drawing of 815 lines, arcs and shapes, not listed
  text "Layer" at 6205.74,3807.5 h60
  text "Name" at 6615.65,3807.5 h60
  text "Material" at 7775.32,3807.5 h60
  text "Thickness" at 8725.06,3807.5 h60
  text "Constant" at 9374.89,3807.5 h60
  text "Board Layer Stack" at 9944.75,3807.5 h60
  text "Top SilkScreen" at 6615.65,3687.5 h60
  text "Top Solder Mask" at 6615.65,3567.5 h60
  text "TAIYO-4000-HFX" at 7775.32,3567.5 h60
  text "0.80mil" at 8725.06,3567.5 h60
  text "3.5" at 9374.89,3567.5 h60
  text "1" at 6205.74,3447.5 h60
  text "Top Copper" at 6615.65,3447.5 h60
  text "1.40mil" at 8725.06,3447.5 h60
  text "Dielectric 1" at 6615.65,3327.5 h60
  text "Meg4" at 7775.32,3327.5 h60
  text "5.10mil" at 8725.06,3327.5 h60
  text "3.83" at 9374.89,3327.5 h60
  text "2" at 6205.74,3207.5 h60
  text "Layer 2 (GND1)" at 6615.65,3207.5 h60
  text "0.70mil" at 8725.06,3207.5 h60
  text "Dielectric 2" at 6615.65,3087.5 h60
  text "FR4-370HR" at 7775.32,3087.5 h60
  text "3.00mil" at 8725.06,3087.5 h60
  text "3.86" at 9374.89,3087.5 h60
  text "3" at 6205.74,2967.5 h60
  text "Layer 3 (PWR1)" at 6615.65,2967.5 h60
  text "1.40mil" at 8725.06,2967.5 h60
  text "Dielectric 3" at 6615.65,2847.5 h60
  text "FR4-370HR" at 7775.32,2847.5 h60
  text "3.00mil" at 8725.06,2847.5 h60
  text "3.72" at 9374.89,2847.5 h60
  text "4" at 6205.74,2727.5 h60
  text "Layer 4 (GND2" at 6615.65,2727.5 h60
  text "0.70mil" at 8725.06,2727.5 h60
  text "Dielectric 4" at 6615.65,2607.5 h60
  text "FR4-370HR" at 7775.32,2607.5 h60
  text "3.00mil" at 8725.06,2607.5 h60
  text "3.86" at 9374.89,2607.5 h60
  text "5" at 6205.74,2487.5 h60
  text "Layer 5 (PWR2)" at 6615.65,2487.5 h60
  text "1.40mil" at 8725.06,2487.5 h60
  text "Dielectric 5" at 6615.65,2367.5 h60
  text "FR4-370HR" at 7775.32,2367.5 h60
  text "3.00mil" at 8725.06,2367.5 h60
  text "3.72" at 9374.89,2367.5 h60
  text "6" at 6205.74,2247.5 h60
  text "Layer 6 (GND3)" at 6615.65,2247.5 h60
  text "CF-004" at 7775.32,2247.5 h60
  text "0.70mil" at 8725.06,2247.5 h60
  text "Dielectric 6" at 6615.65,2127.5 h60
  text "FR4-370HR" at 7775.32,2127.5 h60
  text "3.00mil" at 8725.06,2127.5 h60
  text "3.86" at 9374.89,2127.5 h60
  text "7" at 6205.74,2007.5 h60
  text "Layer 7 (SIG1)" at 6615.65,2007.5 h60
  text "CF-004" at 7775.32,2007.5 h60
  text "1.40mil" at 8725.06,2007.5 h60
  text "Dielectric 7" at 6615.65,1887.5 h60
  text "FR4-370HR" at 7775.32,1887.5 h60
  text "3.00mil" at 8725.06,1887.5 h60
  text "3.72" at 9374.89,1887.5 h60
  text "8" at 6205.74,1767.5 h60
  text "Layer 8 (GND4)" at 6615.65,1767.5 h60
  text "CF-004" at 7775.32,1767.5 h60
  text "1.40mil" at 8725.06,1767.5 h60
  text "Dielectric 8" at 6615.65,1647.5 h60
  text "FR4-370HR" at 7775.32,1647.5 h60
  text "3.00mil" at 8725.06,1647.5 h60
  text "3.86" at 9374.89,1647.5 h60
  text "9" at 6205.74,1527.5 h60
  text "Layer 9 (GND5)" at 6615.65,1527.5 h60
  text "CF-004" at 7775.32,1527.5 h60
  text "0.70mil" at 8725.06,1527.5 h60
  text "Dielectric 9" at 6615.65,1407.5 h60
  text "FR4-370HR" at 7775.32,1407.5 h60
  text "3.00mil" at 8725.06,1407.5 h60
  text "3.72" at 9374.89,1407.5 h60
  text "10" at 6205.74,1287.5 h60
  text "Layer 10 (SIG2)" at 6615.65,1287.5 h60
  text "1.40mil" at 8725.06,1287.5 h60
  text "Dielectric 10" at 6615.65,1167.5 h60
  text "FR4-370HR" at 7775.32,1167.5 h60
  text "3.00mil" at 8725.06,1167.5 h60
  text "3.86" at 9374.89,1167.5 h60
  text "11" at 6205.74,1047.5 h60
  text "Layer 11 (GND6)" at 6615.65,1047.5 h60
  text "0.70mil" at 8725.06,1047.5 h60
  text "Dielectric 11" at 6615.65,927.5 h60
  text "FR4-370HR" at 7775.32,927.5 h60
  text "3.00mil" at 8725.06,927.5 h60
  text "3.72" at 9374.89,927.5 h60
  text "12" at 6205.74,807.5 h60
  text "Layer 12 (PWR3)" at 6615.65,807.5 h60
  text "1.40mil" at 8725.06,807.5 h60
  text "Dielectric 12" at 6615.65,687.5 h60
  text "FR4-370HR" at 7775.32,687.5 h60
  text "3.00mil" at 8725.06,687.5 h60
  text "3.86" at 9374.89,687.5 h60
  text "13" at 6205.74,567.5 h60
  text "Layer 13 (GND7)" at 6615.65,567.5 h60
  text "0.70mil" at 8725.06,567.5 h60
  text "Dielectric 13" at 6615.65,447.5 h60
  text "Meg4" at 7775.32,447.5 h60
  text "5.10mil" at 8725.06,447.5 h60
  text "3.83" at 9374.89,447.5 h60
  text "14" at 6205.74,327.5 h60
  text "Bottom Copper" at 6615.65,327.5 h60
  text "1.40mil" at 8725.06,327.5 h60
  text "Bottom Solder Mask" at 6615.65,207.5 h60
  text "TAIYO-4000-HFX" at 7775.32,207.5 h60
  text "0.80mil" at 8725.06,207.5 h60
  text "3.5" at 9374.89,207.5 h60
  text "Bottom Silk" at 6615.65,87.5 h60
  text "Total board thickness:" at 6205.74,-32.5 h60
  text "60.20mil" at 8725.06,-32.5 h60
  text ".Layer_Name" at 578,-854 h60
M13 Component Bodies Top:
  text ".Layer_Name" at 577,-858.49 h60
M14 Component Bodies Bottom:
  text ".Layer_Name" at 577,-858.49 h60
M15 Courtyards Top:
  text ".Layer_Name" at 577,-858.49 h60
M16 Courtyards Bottom:
  text ".Layer_Name" at 577,-858.49 h60
Drill Drawing:
  drawing of 165 lines, arcs and shapes, not listed
  text "Symbol" at 120.46,6468.59 h96
  text "Quantity" at 521.21,6468.59 h96
  text "Finished Hole Size" at 963.88,6468.59 h96
  text "Plated" at 1812.63,6468.59 h96
  text "Hole Type" at 2158.15,6468.59 h96
  text "Drill Layer Pair" at 2658.36,6468.59 h96
  text "114" at 521.21,6302.83 h80
  text "7.87mil (0.200mm)" at 963.88,6302.83 h80
  text "PTH" at 1812.63,6302.83 h80
  text "Round" at 2158.15,6302.83 h80
  text "Top Copper - Bottom Copper" at 2658.36,6302.83 h80
  text "759" at 521.21,6137.07 h80
  text "8.00mil (0.203mm)" at 963.88,6137.07 h80
  text "PTH" at 1812.63,6137.07 h80
  text "Round" at 2158.15,6137.07 h80
  text "Top Copper - Bottom Copper" at 2658.36,6137.07 h80
  text "245" at 521.21,5971.31 h80
  text "8.00mil (0.203mm)" at 963.88,5971.31 h80
  text "PTH" at 1812.63,5971.31 h80
  text "Round" at 2158.15,5971.31 h80
  text "Top Copper - Bottom Copper" at 2658.36,5971.31 h80
  text "E" at 89.03,5961.32 h73.67
  text "30" at 521.21,5805.55 h80
  text "15.00mil (0.381mm)" at 963.88,5805.55 h80
  text "PTH" at 1812.63,5805.55 h80
  text "Round" at 2158.15,5805.55 h80
  text "Top Copper - Bottom Copper" at 2658.36,5805.55 h80
  text "20" at 521.21,5639.79 h80
  text "15.75mil (0.400mm)" at 963.88,5639.79 h80
  text "PTH" at 1812.63,5639.79 h80
  text "Round" at 2158.15,5639.79 h80
  text "Top Copper - Bottom Copper" at 2658.36,5639.79 h80
  text "C" at 89.03,5629.8 h73.67
  text "31" at 521.21,5474.03 h80
  text "28.00mil (0.711mm)" at 963.88,5474.03 h80
  text "PTH" at 1812.63,5474.03 h80
  text "Round" at 2158.15,5474.03 h80
  text "Top Copper - Bottom Copper" at 2658.36,5474.03 h80
  text "J" at 89.03,5464.04 h73.67
  text "2" at 521.21,5308.27 h80
  text "29.92mil (0.760mm)" at 963.88,5308.27 h80
  text "PTH" at 1812.63,5308.27 h80
  text "Slot" at 2158.15,5308.27 h80
  text "Top Copper - Bottom Copper" at 2658.36,5308.27 h80
  text "1" at 521.21,5142.51 h80
  text "39.76mil (1.010mm)" at 963.88,5142.51 h80
  text "PTH" at 1812.63,5142.51 h80
  text "Slot" at 2158.15,5142.51 h80
  text "Top Copper - Bottom Copper" at 2658.36,5142.51 h80
  text "4" at 521.21,4976.75 h80
  text "40.00mil (1.016mm)" at 963.88,4976.75 h80
  text "PTH" at 1812.63,4976.75 h80
  text "Round" at 2158.15,4976.75 h80
  text "Top Copper - Bottom Copper" at 2658.36,4976.75 h80
  text "2" at 521.21,4810.99 h80
  text "40.16mil (1.020mm)" at 963.88,4810.99 h80
  text "NPTH" at 1812.63,4810.99 h80
  text "Round" at 2158.15,4810.99 h80
  text "Top Copper - Bottom Copper" at 2658.36,4810.99 h80
  text "2" at 521.21,4645.23 h80
  text "50.00mil (1.270mm)" at 963.88,4645.23 h80
  text "NPTH" at 1812.63,4645.23 h80
  text "Round" at 2158.15,4645.23 h80
  text "Top Copper - Bottom Copper" at 2658.36,4645.23 h80
  text "2" at 521.21,4479.47 h80
  text "63.00mil (1.600mm)" at 963.88,4479.47 h80
  text "PTH" at 1812.63,4479.47 h80
  text "Round" at 2158.15,4479.47 h80
  text "Top Copper - Bottom Copper" at 2658.36,4479.47 h80
  text "G" at 89.03,4469.48 h73.67
  text "12" at 521.21,4313.71 h80
  text "66.93mil (1.700mm)" at 963.88,4313.71 h80
  text "PTH" at 1812.63,4313.71 h80
  text "Round" at 2158.15,4313.71 h80
  text "Top Copper - Bottom Copper" at 2658.36,4313.71 h80
  text "A" at 89.03,4303.72 h73.67
  text "3" at 521.21,4147.95 h80
  text "72.84mil (1.850mm)" at 963.88,4147.95 h80
  text "PTH" at 1812.63,4147.95 h80
  text "Round" at 2158.15,4147.95 h80
  text "Top Copper - Bottom Copper" at 2658.36,4147.95 h80
  text "2" at 521.21,3982.19 h80
  text "96.46mil (2.450mm)" at 963.88,3982.19 h80
  text "NPTH" at 1812.63,3982.19 h80
  text "Round" at 2158.15,3982.19 h80
  text "Top Copper - Bottom Copper" at 2658.36,3982.19 h80
  text "2" at 521.21,3816.43 h80
  text "105.91mil (2.690mm)" at 963.88,3816.43 h80
  text "NPTH" at 1812.63,3816.43 h80
  text "Round" at 2158.15,3816.43 h80
  text "Top Copper - Bottom Copper" at 2658.36,3816.43 h80
  text "2" at 521.21,3650.67 h80
  text "125.98mil (3.200mm)" at 963.88,3650.67 h80
  text "NPTH" at 1812.63,3650.67 h80
  text "Round" at 2158.15,3650.67 h80
  text "Top Copper - Bottom Copper" at 2658.36,3650.67 h80
  text "1233 Total" at 521.21,3484.91 h80
  text "Slot definitions :" at 120.46,3368.88 h80
  text "Routed Path Length" at 721.41,3368.88 h80
  text "= Calculated from tool start centre position to tool end centre position." at 1441.06,3368.88 h80
  text "Hole Length" at 721.41,3302.57 h80
  text "= Routed Path Length + Tool Size = Slot length as defined in the PCB layout" at 1174.66,3302.57 h80
  text ".Layer_Name" at 576,-851 h60
Mechanical 17:
  rectangle: 2020.1,1591.3 2033.1,1604.3
  region: 2187.63,2113.73 2193.5,2119.6 2187.63,2125.47 2181.76,2119.6
  region: 3293.53,2238.03 3299.4,2243.9 3293.53,2249.77 3287.66,2243.9
  rectangle: 385.8,563.2 398.8,576.2
  region: 390.61,589.61 399.8,598.8 390.61,607.99 381.42,598.8
  rectangle: 6048.4,1647.55 6057.1,1656.25
  region: 3773.9,1979.2 3773.9,1970.9 3782.2,1970.9 3782.2,1979.2

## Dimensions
4190,2750 to 0,0 on M2 Board Dimensions
0,0 to 0,2750 on M2 Board Dimensions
